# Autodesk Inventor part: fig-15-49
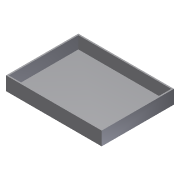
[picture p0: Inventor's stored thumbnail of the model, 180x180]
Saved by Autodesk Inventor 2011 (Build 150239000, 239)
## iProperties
Shininess: 77.0
Angle Display Precision: 2
Document Length Units: 11269
Document Angle Units: 11279
Document Time Units: 11290
Document Mass Units: 11283
Document Length Units Precision: 3
Document Angle Units Precision: 2
Compacted: True
Created: 2002-04
Part Number: fig-15-49
Document SubType Name: Sheet Metal
Density: 1 g/cm^3
Sheet Metal Rule: Default
Density: 0.0
Volumn: 0.0
Area: 0.0
PropertySet Name: Model Information
Control State: 0
Master: False
Checked Out: False
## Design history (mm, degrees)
sketch "Sketch1"
  geometry: L1 (-34, 28)-(36, 28); L2 (36, 28)-(36, -24.941); L3 (36, -24.941)-(-34, -24.941); L4 (-34, -24.941)-(-34, 28)
  constraints: 8 end point, 2 parallel, 1 horizontal, 1 perpendicular
extrude "Extrusion1" new body sketch "Sketch1" distance "d0" = 10; taper "d1" = 0 deg
shell "Shell1" dims "d2" = 1
body "Solid1"
other parameters: "Thickness" = 1, "BendRadius" = 1 (= Thickness), "BendReliefWidth" = 1 (= Thickness), "BendReliefDepth" = 0.5 (= 0.5 x Thickness), "CornerReliefSize" = 4 (= 4 x Thickness), "SeamGap" = 0.01, "MinimumRemnant" = 2 (= 2 x Thickness), "TransitionRadius" = 1 (= BendRadius), "JacobiRadiusSize" = 1 (= Thickness), "GapSize" = 1 (= Thickness)
